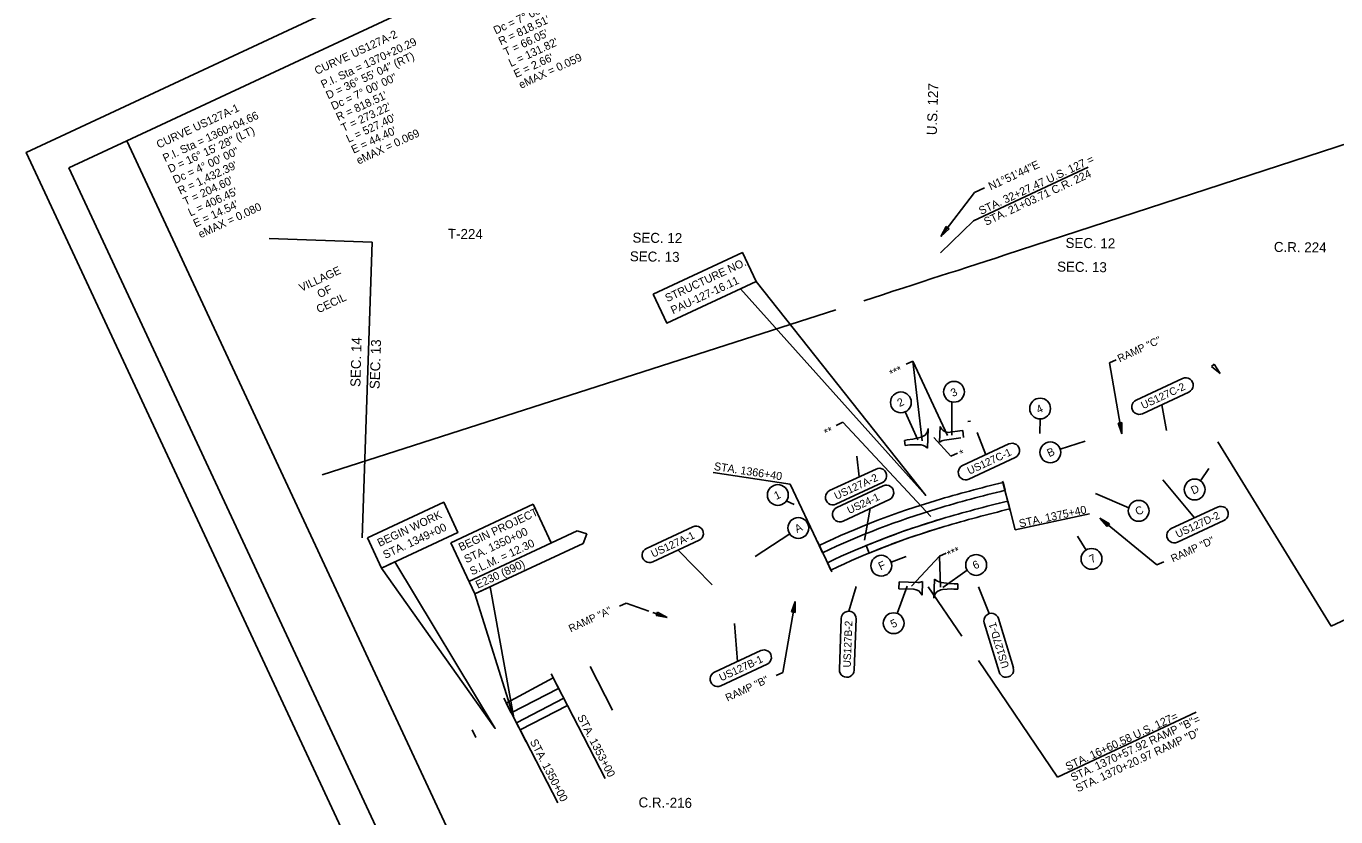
# Model space of a CAD drawing. Extents: x -310467776 to 1403491, y -322263105 to 578683.
# Drawn here: x 1391457 to 1397595, y 571259 to 574964 of the extents above; entities that cross this region are included whole.
import ezdxf

# ---------------------------------------------------------------- set-up
doc = ezdxf.new("R2010")
doc.units = 0
for name, color, linetype in [('DV_X_Section_VMS_Line', 7, 'Continuous'), ('Level 4', 7, 'Continuous'), ('Level 40', 7, 'Continuous'), ('RD_X_RR_1', 7, 'Continuous'), ('SC_Scratch1', 7, 'Continuous'), ('SC_Shading2', 7, 'Continuous'), ('SH_Border', 7, 'Continuous'), ('SH_Cut_Line', 7, 'Continuous'), ('SH_Text', 7, 'Continuous')]:
    doc.layers.add(name, color=color, linetype=linetype)

msp = doc.modelspace()

# ---------------------------------------------------------------- linework, layer by layer
at = {"layer": 'DV_X_Section_VMS_Line'}
for p, q in [((1392596.5, 573969.5), (1393079.2, 573952.5)), ((1393079.2, 573952.5), (1393031, 572566.5))]:
    msp.add_line(p, q, dxfattribs=at)
at = {"layer": 'Level 4'}
msp.add_line((1393564.9, 571631.4), (1393546.5, 571667), dxfattribs=at)
at = {"layer": 'Level 40'}
for p, q in [((1395744.2, 573979.6), (1395768.8, 574025.7)), ((1395782.4, 574015.2), (1395744.2, 573979.6)), ((1395768.8, 574025.7), (1395782.4, 574015.2)), ((1397011.9, 573368.9), (1397024.6, 573380.5)), ((1397052.9, 573336.6), (1397011.9, 573368.9)), ((1397024.6, 573380.5), (1397052.9, 573336.6)), ((1396575, 573104), (1396591.9, 573107)), ((1396592.4, 573054.7), (1396575, 573104)), ((1396591.9, 573107), (1396592.4, 573054.7)), ((1396523.6, 572619.6), (1396489.1, 572659)), ((1396489.1, 572659), (1396534.5, 572632.9)), ((1396534.5, 572632.9), (1396523.6, 572619.6)), ((1395044.4, 572219.6), (1395061.7, 572268.9)), ((1395061.7, 572268.9), (1395061.3, 572216.6)), ((1394409.8, 572202.6), (1394415.5, 572218.8)), ((1394461.3, 572193.5), (1394409.8, 572202.6)), ((1394415.5, 572218.8), (1394461.3, 572193.5)), ((1395061.3, 572216.6), (1395044.4, 572219.6))]:
    msp.add_line(p, q, dxfattribs=at)
at = {"layer": 'RD_X_RR_1'}
for points in [[(1396045.7, 573892.7), (1398068.9, 574551.5), (1399780.9, 575107.6), (1401168.4, 575558.4)], [(1396045.7, 573892.7), (1396001, 573878), (1395955.5, 573863.3), (1395911.8, 573849.1), (1395869, 573835.4), (1395822.7, 573820.2), (1395779.4, 573806.3), (1395701.9, 573781.3), (1395656.3, 573766.5), (1395613.9, 573752.9), (1395565.1, 573737), (1395519.2, 573722.1), (1395469.5, 573705.8), (1395382.4, 573677.8)], [(1395251.1, 573635.6), (1392843.7, 572861.4)]]:
    msp.add_lwpolyline(points, dxfattribs=at)
at = {"layer": 'SC_Scratch1'}
for p, q in [((1396033.3, 572833), (1396068.3, 572695.3)), ((1395165.2, 572548.9), (1395232.2, 572407.1)), ((1394205.3, 571759.7), (1394099.8, 571963.8)), ((1394022.6, 571726), (1393917, 571930.1)), ((1393800.5, 571611.1), (1393695, 571815.2))]:
    msp.add_line(p, q, dxfattribs=at)
at = {"layer": 'SC_Shading2'}
for p, q in [((1395882.7, 573113.6), (1395869.7, 573111.9)), ((1395684.2, 573079.7), (1395680.8, 572987.1)), ((1395737.9, 573015), (1395740.6, 573088.1)), ((1395787.3, 573061.3), (1395832.6, 573067.6)), ((1395832.6, 573067.6), (1395846.1, 573069.4)), ((1395846.1, 573069.4), (1395850.1, 573036.6)), ((1395572.6, 573023.4), (1395586, 573025.4)), ((1395576.5, 572998.7), (1395572.6, 573023.4)), ((1395597.6, 573001.8), (1395576.5, 572998.7)), ((1395586, 573025.4), (1395611.7, 573028.9)), ((1395639.6, 573003), (1395597.6, 573001.8)), ((1395611.7, 573028.9), (1395650.9, 573038.7)), ((1395837.1, 573034.9), (1395760.1, 573024.3)), ((1396044.4, 572789.5), (1396035, 572826.3)), ((1396066.5, 572702.2), (1396057.2, 572739.1)), ((1395173.4, 572531.6), (1395189.6, 572497.2)), ((1395408, 572495.3), (1395393.6, 572530.5)), ((1395211.9, 572450.2), (1395228.1, 572415.8)), ((1395710.9, 572284.3), (1395714.2, 572373.4)), ((1395546.4, 572328.2), (1395547.6, 572361.2)), ((1395616.4, 572325.6), (1395546.4, 572328.2)), ((1395547.6, 572361.2), (1395635.6, 572357.9)), ((1395657.8, 572362.6), (1395655.4, 572298.5)), ((1395745.2, 572358.2), (1395783.1, 572352.5)), ((1395795.5, 572327), (1395752.2, 572324.4)), ((1395783.1, 572352.5), (1395806.1, 572351.6)), ((1395805.2, 572326.6), (1395795.5, 572327)), ((1395806.1, 572351.6), (1395823.1, 572351.6)), ((1395823.1, 572351.6), (1395823.1, 572326.2))]:
    msp.add_line(p, q, dxfattribs=at)
for points in [[(1393730.6, 571746.4), (1393707, 571792), (1393926.8, 571911.2), (1393952.6, 571861.3)], [(1393771.9, 571666.5), (1393754.5, 571700.2), (1393976.5, 571815.1), (1393994, 571781.3)]]:
    msp.add_lwpolyline(points, close=True, dxfattribs=at)
for centre, radius, start, end in [((1395640.3, 573081.4), 44, 283.91662, 357.885), ((1395781.2, 573104.9), 44, 202.50498, 277.885), ((1395641.3, 572946), 57, 46.07469, 91.67637), ((1395766.5, 572977.7), 47, 97.885, 127.55002), ((1397786, 565693), 7345.1, 103.79136, 106.31863), ((1396835.3, 569021.1), 3884, 106.6545, 115.33402), ((1397439, 567013.7), 5941.8, 103.57511, 106.77049), ((1396840.8, 568998.7), 3868.6, 106.77049, 115.26589), ((1397799.7, 565642), 7307.9, 103.79508, 106.3062), ((1397803.9, 565626.5), 7285.9, 103.79553, 106.3017), ((1396835.3, 569021.1), 3794, 106.65556, 115.33437), ((1396835.3, 569021.1), 3756, 106.65555, 115.33453), ((1396835.2, 569021.3), 3793.7, 106.65544, 112.33482), ((1396835.2, 569021.4), 3755.7, 106.65544, 112.33483), ((1395753.7, 572414.6), 57, 226.07469, 261.33516), ((1395614.7, 572281.6), 44, 22.50498, 87.88501), ((1395637.3, 572404.9), 47, 267.88501, 295.79507), ((1395754.8, 572280.3), 44.1, 93.49578, 174.83494), ((1395831.9, 573048.3), 722.2, 267.885, 269.30747)]:
    msp.add_arc(centre, radius, start, end, dxfattribs=at)
at = {"layer": 'SH_Border'}
for points in [[(1391928.5, 574427), (1400629, 578484.1), (1403291.5, 572774.4), (1394591, 568717.3)], [(1391656.6, 574300.2), (1391928.5, 574427), (1394591, 568717.3), (1394319.1, 568590.5)]]:
    msp.add_lwpolyline(points, close=True, dxfattribs=at)
at = {"layer": 'SH_Cut_Line'}
msp.add_lwpolyline([(1394246.5, 568391.1), (1403490.9, 572701.8), (1400701.6, 578683.5), (1391457.2, 574372.8)], close=True, dxfattribs=at)
at = {"layer": 'SH_Text'}
for p, q in [((1395896.6, 574052.5), (1396434.7, 574303.5)), ((1395896.6, 574052.5), (1395741.7, 573902.9)), ((1395580.5, 573380.6), (1395612, 573395.3)), ((1395656.2, 573021.3), (1395612, 573395.3)), ((1395775.6, 573045.6), (1395612, 573395.3)), ((1396533.8, 573386.6), (1396565.4, 573401.3)), ((1396533.8, 573386.6), (1396592.4, 573054.7)), ((1396659, 573211.9), (1396876.5, 573313.3)), ((1396906.1, 573249.9), (1396688.5, 573148.4)), ((1396906.1, 573249.9), (1396906.1, 573249.9)), ((1395795.9, 573203.4), (1395795.6, 573048.4)), ((1396778.9, 573190.6), (1396800.7, 573069.2)), ((1395252.9, 573093.5), (1395284.5, 573108.2)), ((1395697, 572667.5), (1395284.5, 573108.2)), ((1395576.6, 573157), (1395635.8, 573026.2)), ((1396208.4, 573123.8), (1396207.6, 573055.6)), ((1395913.2, 573060.8), (1395954.2, 572956.1)), ((1395710.7, 573036.6), (1395790.7, 572949.4)), ((1395845.4, 572905.4), (1396062.9, 573006.8)), ((1396303.3, 572982), (1396420.6, 573019.3)), ((1397041, 573015.9), (1397573.1, 572153)), ((1395361.3, 572852.6), (1395350.4, 572949.2)), ((1395790.7, 572949.4), (1395822.2, 572964.1)), ((1396092.5, 572943.4), (1395875, 572841.9)), ((1396092.5, 572943.4), (1396092.5, 572943.4)), ((1395037.7, 572818.2), (1394675.9, 572873.5)), ((1395222.5, 572787.9), (1395440, 572889.3)), ((1396960.3, 572833.6), (1396999.3, 572891.9)), ((1395173.4, 572531.6), (1395037.7, 572818.2)), ((1395469.6, 572825.9), (1395252.1, 572724.4)), ((1395255.7, 572708.7), (1395473.2, 572810.2)), ((1395469.6, 572825.9), (1395469.6, 572825.9)), ((1396931.9, 572660.5), (1396783.4, 572838.8)), ((1395502.8, 572746.7), (1395285.3, 572645.3)), ((1395502.8, 572746.7), (1395502.8, 572746.7)), ((1396469.2, 572775.1), (1396624.2, 572707.8)), ((1393447.5, 572544.1), (1393833.7, 572724.3)), ((1393918.2, 572543), (1393833.7, 572724.3)), ((1395019.5, 572739.4), (1395055.9, 572723.4)), ((1395412.2, 572704.5), (1395386.1, 572555.5)), ((1396066.5, 572702.2), (1396091.3, 572604.7)), ((1396091.3, 572604.7), (1396440.4, 572679.7)), ((1396823.1, 572609.8), (1397040.7, 572711.2)), ((1394363.7, 572517.1), (1394581.2, 572618.5)), ((1396756.4, 572439.8), (1396489.1, 572659)), ((1397070.2, 572647.7), (1396852.7, 572546.3)), ((1397070.2, 572647.7), (1397070.2, 572647.7)), ((1393532, 572362.9), (1394039.5, 572599.6)), ((1393532, 572362.9), (1394039.5, 572599.6)), ((1394039.5, 572599.6), (1394084.7, 572585.5)), ((1394067, 572540.6), (1394084.7, 572585.5)), ((1395035.3, 572586), (1394873, 572478.8)), ((1396424.1, 572509.5), (1396384.1, 572574)), ((1393447.5, 572544.1), (1393559.4, 572304)), ((1393559.4, 572304), (1394067, 572540.6)), ((1394610.8, 572555.1), (1394393.3, 572453.7)), ((1394513.1, 572509.5), (1394671.7, 572346)), ((1394610.8, 572555.1), (1394610.8, 572555.1)), ((1395769.3, 572495), (1395737.7, 572480.3)), ((1395510.1, 572453.3), (1395580.6, 572479.9)), ((1395606.8, 572340), (1395737.7, 572480.3)), ((1395741.6, 572335), (1395737.7, 572480.3)), ((1396756.4, 572439.8), (1396787.9, 572454.5)), ((1395866.7, 572415.5), (1395752.5, 572334.6)), ((1397573.1, 572153), (1398115.3, 572405.8)), ((1395313.1, 572223.2), (1395346.4, 572338.5)), ((1395539.1, 572212.3), (1395585.6, 572340.7)), ((1395684.8, 572337.1), (1395842.1, 572105.7)), ((1395970.5, 572211.5), (1395920.6, 572337.7)), ((1394238.2, 572246.2), (1394269.7, 572261)), ((1394269.7, 572261), (1394375.2, 572223.8)), ((1395003.7, 571936.2), (1395061.7, 572268.9)), ((1395003.7, 571936.2), (1395061.7, 572268.9)), ((1394394.7, 572217), (1394461.3, 572193.5)), ((1395268, 571949.7), (1395276.9, 572189.5)), ((1396014.1, 572188.1), (1396083.4, 571958.3)), ((1396014.1, 572188.1), (1396014.1, 572188.1)), ((1394791.2, 571987.6), (1394776.2, 572165.8)), ((1395346.8, 572186.9), (1395338, 571947.1)), ((1395346.8, 572186.9), (1395346.8, 572186.9)), ((1396016.3, 571938.1), (1395947, 572167.9)), ((1394682.4, 571936.9), (1394900, 572038.3)), ((1394929.5, 571974.9), (1394712, 571873.5)), ((1394929.5, 571974.9), (1394929.5, 571974.9)), ((1395919.8, 571991.3), (1396290.5, 571445.8)), ((1394972.1, 571921.5), (1395003.7, 571936.2)), ((1393994, 571781.3), (1394171.1, 571439)), ((1396290.5, 571445.8), (1396940.9, 571749.1)), ((1393771.9, 571666.5), (1393949, 571324.2))]:
    msp.add_line(p, q, dxfattribs=at)
msp.add_lwpolyline([(1395948.1, 574206.3), (1395902.1, 574184.9), (1395744.2, 573979.6)], dxfattribs=at)
for points in [[(1394396.1, 573708.9), (1394814.1, 573903.8), (1394877.5, 573767.8), (1394459.5, 573572.9)], [(1394805.4, 573734.2), (1395673.3, 572765.5), (1394877.5, 573767.8)], [(1393056.5, 572566.7), (1393413.7, 572733.3), (1393479.8, 572591.4), (1393122.6, 572424.9)], [(1393122.6, 572424.9), (1393655.5, 571673.7), (1393185.3, 572454.1)], [(1393559.4, 572304), (1393742.5, 571723.3), (1393631.5, 572337.6)]]:
    msp.add_lwpolyline(points, close=True, dxfattribs=at)
for centre in [(1395805.2, 573251.2), (1395556.5, 573201.4), (1396208.9, 573172.5), (1396256.8, 572967.2), (1394979.7, 572767.4), (1396933.2, 572793.1), (1396670.7, 572693.4), (1395075.9, 572612.9), (1396449.8, 572468), (1395464.5, 572436.1), (1395909.1, 572439.7), (1395522.5, 572166.5)]:
    msp.add_circle(centre, 48.8, dxfattribs=at)
for centre, start, end in [((1396891.3, 573281.6), 294.99958, 115), ((1396673.8, 573180.2), 115, 295.00042), ((1396077.7, 572975.1), 294.99958, 115), ((1395454.8, 572857.6), 294.99958, 115), ((1395860.2, 572873.6), 115, 295.00042), ((1395488, 572778.4), 294.99958, 115), ((1395237.3, 572756.2), 115, 295.00042), ((1395270.5, 572677), 115, 295.00042), ((1397055.4, 572679.5), 294.99958, 115), ((1394596, 572586.8), 294.99958, 115), ((1396837.9, 572578), 115, 295.00042), ((1394378.5, 572485.4), 115, 295.00042), ((1395311.8, 572188.2), 357.88458, 177.885), ((1395980.6, 572178), 16.77979, 196.78021), ((1394914.7, 572006.6), 294.99958, 115), ((1395303, 571948.4), 177.885, 357.88542), ((1396049.8, 571948.2), 196.78021, 16.78063), ((1394697.2, 571905.2), 115, 295.00042)]:
    msp.add_arc(centre, 35, start, end, dxfattribs=at)

# ---------------------------------------------------------------- texts
for s, height, rotation, p in [('Dc = 7° 00\' 00"', 37.5, 25, (1393657.5, 574925.4)), ("R = 818.51'", 37.5, 25, (1393681.2, 574874.4)), ("T = 66.05'", 37.5, 25, (1393705, 574823.5)), ('CURVE US127A-2', 37.5, 25, (1392819.2, 574735.9)), ('P.I. Sta = 1370+20.29', 37.5, 25, (1392848.8, 574672.4)), ("L = 131.82'", 37.5, 25, (1393728.8, 574772.5)), ('D = 36° 55\' 04" (RT)', 37.5, 25, (1392872.5, 574621.5)), ("E = 2.66'", 37.5, 25, (1393752.5, 574721.5)), ('eMAX = 0.059', 37.5, 25, (1393776.3, 574670.5)), ('Dc = 7° 00\' 00"', 37.5, 25, (1392896.3, 574570.5)), ("R = 818.51'", 37.5, 25, (1392920.1, 574519.5)), ('U.S. 127', 46.8, 88.16758, (1395724.4, 574452.9)), ('CURVE US127A-1', 37.5, 25, (1392078.4, 574390.5)), ("T = 273.22'", 37.5, 25, (1392943.8, 574468.5)), ('P.I. Sta = 1360+04.66', 37.5, 25, (1392108, 574327)), ("L = 527.40'", 37.5, 25, (1392967.6, 574417.5)), ('D = 16° 15\' 28" (LT)', 37.5, 25, (1392131.8, 574276)), ("E = 44.40'", 37.5, 25, (1392991.4, 574366.6)), ('eMAX = 0.069', 37.5, 25, (1393015.2, 574315.6)), ('Dc = 4° 00\' 00"', 37.5, 25, (1392155.5, 574225.1)), ('STA. 32+27.47 U.S. 127 =', 37.5, 25, (1395932.2, 574079.6)), ('N1°51\'44"E', 37.5, 25, (1395977.5, 574194.7)), ("R = 1,432.39'", 37.5, 25, (1392179.3, 574174.1)), ('STA. 21+03.71 C.R. 224', 37.5, 25, (1395955.9, 574028.6)), ("T = 204.60'", 37.5, 25, (1392203.1, 574123.1)), ("L = 406.45'", 37.5, 25, (1392226.9, 574072.1)), ("E = 14.54'", 37.5, 25, (1392250.6, 574021.1)), ('eMAX = 0.080', 37.5, 25, (1392274.4, 573970.2)), ('T-224', 46.8, 359.37011, (1393433.3, 573968.2)), ('SEC. 12', 46.8, 359.37011, (1394298.4, 573950.2)), ('SEC. 12', 46.8, 359.37011, (1396327.8, 573925.7)), ('SEC. 13', 46.8, 359.19051, (1394285.9, 573862.9)), ('C.R. 224', 46.8, 359.37011, (1397304.1, 573906.7)), ('STRUCTURE NO.', 37.5, 25, (1394462.1, 573670.7)), ('SEC. 13', 46.8, 359.19051, (1396288.2, 573814.6)), ('VILLAGE', 37.5, 25, (1392746.7, 573719)), ('PAU-127-16.11', 37.5, 25, (1394488.5, 573614)), ('OF', 37.5, 25, (1392831.7, 573689.7)), ('CECIL', 37.5, 25, (1392827.7, 573618.8)), ('SEC. 14', 46.8, 88.43219, (1393023.2, 573273.1)), ('SEC. 13', 46.8, 88.20016, (1393113.3, 573263)), ('RAMP "C"', 35.5, 25, (1396581.6, 573388.8)), ('***', 37.5, 25, (1395513.3, 573316.7)), ('3', 37.5, 25, (1395800.2, 573226)), ('US127C-2', 35.5, 25, (1396691.7, 573169.1)), ('2', 37.5, 25, (1395549.6, 573179.2)), ('4', 37.5, 25, (1396201.2, 573148.1)), ('**', 37.5, 25, (1395207, 573039.4)), ('B', 37.5, 25, (1396251.7, 572944.1)), ('*', 37.5, 25, (1395842.2, 572941.5)), ('US127C-1', 35.5, 25, (1395877.6, 572862.2)), ('STA. 1366+40', 37.5, 351.31408, (1394678.5, 572884.8)), ('US127A-2', 35.5, 25, (1395254.1, 572744.4)), ('D', 37.5, 25, (1396926.2, 572769.2)), ('1', 37.5, 25, (1394972.4, 572744.3)), ('US24-1', 35.5, 25, (1395314.4, 572677.9)), ('BEGIN WORK', 37.5, 25, (1393113.3, 572524.2)), ('BEGIN PROJECT', 37.5, 24.99996, (1393493.9, 572503.7)), ('STA. 1375+40', 37.5, 12.11879, (1396114.2, 572614.8)), ('C', 37.5, 25, (1396665.1, 572670.1)), ('US127D-2', 35.5, 25, (1396853.7, 572565.8)), ('STA. 1349+00', 37.5, 25, (1393139.7, 572467.6)), ('A', 37.5, 25, (1395069.3, 572589.1)), ('STA. 1350+00', 37.5, 24.99996, (1393520.3, 572447.1)), ('S.L.M. = 12.30', 37.5, 24.99996, (1393546.7, 572390.4)), ('US127A-1', 35.5, 25, (1394395.2, 572473.6)), ('RAMP "D"', 35.5, 25, (1396831.5, 572451)), ('***', 37.5, 25, (1395784.3, 572469.4)), ('E230 (890)', 37.5, 24.99996, (1393573.9, 572327.6)), ('F', 37.5, 25, (1395461.4, 572413.9)), ('6', 37.5, 25, (1395903.1, 572417.8)), ('7', 37.5, 25, (1396449.9, 572446.7)), ('RAMP "A"', 35.5, 25, (1394009.3, 572123.1)), ('US127B-2', 35.5, 87.88501, (1395321.1, 571958.9)), ('5', 37.5, 25, (1395518, 572142.8)), ('US127D-1', 35.5, 106.78021, (1396064.2, 571961.9)), ('US127B-1', 35.5, 25, (1394714.7, 571893.7)), ('RAMP "B"', 35.5, 25, (1394744, 571798.7)), ('STA. 1353+00', 37.5, 297.35147, (1394038.6, 571726.9)), ('STA. 16+60.58 U.S. 127=', 37.5, 25, (1396338.5, 571475.5)), ('STA. 1370+57.92 RAMP "B"=', 37.5, 25, (1396362.2, 571424.5)), ('STA. 1370+20.97 RAMP "D"', 37.5, 25, (1396386, 571373.6)), ('STA. 1350+00', 37.5, 297.35147, (1393816.6, 571612)), ('C.R.-216', 46.8, 359.37011, (1394326.8, 571303.8))]:
    msp.add_text(s, height=height, rotation=rotation, dxfattribs=at).set_placement(p)

doc.saveas('drawing.dxf')
